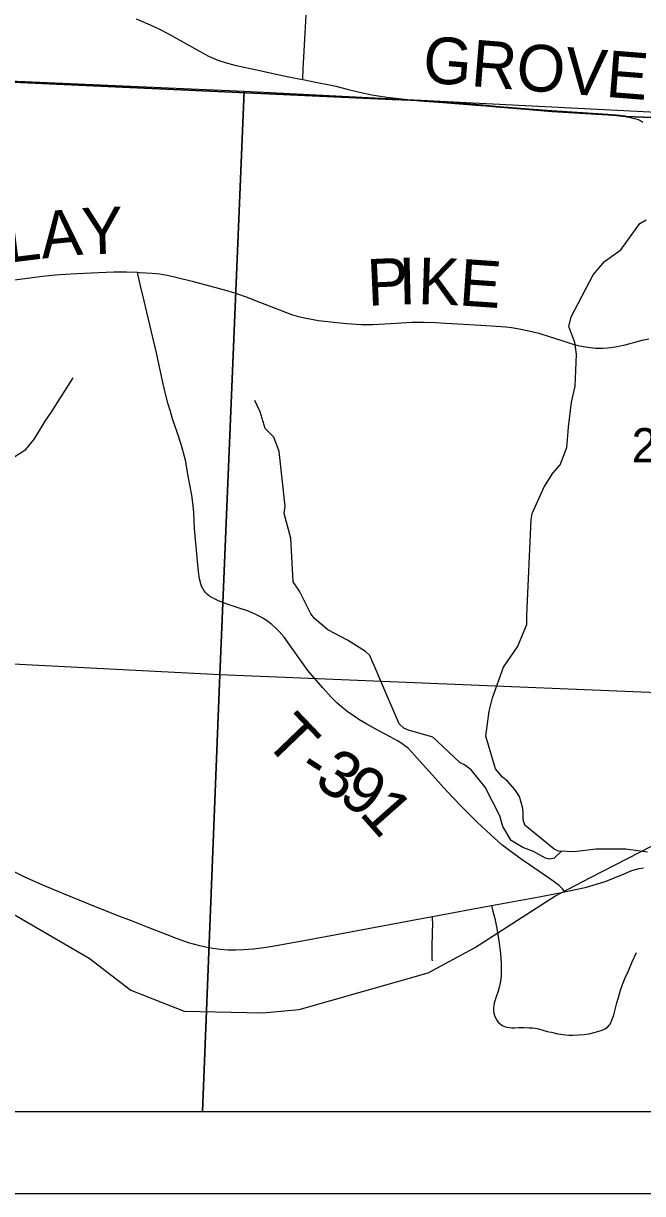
# Model space of a CAD drawing. Extents: x 0 to 34, y 0 to 22.
# Drawn here: x 3.463 to 4.217, y 14 to 15.425 of the extents above; entities that cross this region are included whole.
import ezdxf

# ---------------------------------------------------------------- set-up
doc = ezdxf.new("R2010")
doc.units = 0
for name, color, linetype in [('GM_X_County_Road', 7, 'Continuous'), ('GM_X_County_Road_Text', 7, 'Continuous'), ('GM_X_Minor_River', 7, 'Continuous'), ('GM_X_Rail_Line', 7, 'Continuous'), ('GM_X_Section', 7, 'Continuous'), ('GM_X_Section_Text', 7, 'Continuous'), ('GM_X_State_Route', 7, 'Continuous'), ('GM_X_Township_Road', 7, 'Continuous'), ('GM_X_Township_Road_Text', 7, 'Continuous'), ('GM_X_Unincorporated_Text', 7, 'Continuous'), ('SH_Data', 7, 'Continuous')]:
    doc.layers.add(name, color=color, linetype=linetype)

msp = doc.modelspace()

# ---------------------------------------------------------------- linework, layer by layer
at = {"layer": 'GM_X_County_Road'}
for points in [[(3.6001, 15.4304), (3.6172, 15.4233), (3.6284, 15.418), (3.6394, 15.4122), (3.6773, 15.391), (3.6882, 15.3851), (3.6938, 15.3825), (3.6995, 15.3802), (3.7083, 15.3774), (3.7203, 15.3743), (3.7506, 15.3676), (3.7779, 15.3617), (3.7961, 15.3578), (3.803, 15.3565)], [(3.803, 15.3565), (3.8205, 15.3532), (3.8334, 15.3506), (3.8434, 15.3484), (3.8571, 15.3451), (3.8719, 15.3411), (3.8871, 15.3381), (3.9054, 15.3351), (3.9236, 15.333), (3.9453, 15.3308), (3.9733, 15.3285), (4.0135, 15.3256), (4.0259, 15.3246), (4.0383, 15.3234), (4.0785, 15.3201), (4.1063, 15.3179), (4.1745, 15.3136), (4.1851, 15.3127), (4.1958, 15.3116), (4.1975, 15.3113), (4.2024, 15.3104), (4.2034, 15.3101)], [(4.2034, 15.3101), (4.2085, 15.3089), (4.2115, 15.3078), (4.2144, 15.3064), (4.2171, 15.3048)]]:
    msp.add_lwpolyline(points, dxfattribs=at)
at = {"layer": 'GM_X_Minor_River'}
for points in [[(4.2227, 14.4157), (4.1962, 14.4193), (4.1773, 14.4196), (4.1596, 14.4195), (4.1335, 14.4163), (4.1142, 14.417), (4.1092, 14.4192), (4.0735, 14.4486), (4.0712, 14.4555), (4.0712, 14.4638), (4.0708, 14.4691), (4.0669, 14.4835), (4.0612, 14.4922), (4.0521, 14.5024), (4.046, 14.507), (4.0376, 14.5172), (4.0257, 14.557), (4.0301, 14.5874), (4.0338, 14.6037), (4.0472, 14.641), (4.0645, 14.6658), (4.0757, 14.6928), (4.0756, 14.7038), (4.0811, 14.8208), (4.0822, 14.828), (4.0964, 14.86), (4.1073, 14.8771), (4.1163, 14.8874), (4.1245, 14.9087), (4.1259, 14.9281), (4.1263, 14.9334), (4.1303, 14.9638), (4.1347, 14.9832), (4.1364, 15.0223), (4.1341, 15.0364), (4.1268, 15.0561), (4.1298, 15.0675), (4.1564, 15.1189), (4.1703, 15.1349), (4.1902, 15.1494), (4.2132, 15.1815), (4.2211, 15.1857)], [(3.4433, 14.8917), (3.4656, 14.9063), (3.4765, 14.9193), (3.4892, 14.9406), (3.4964, 14.9513), (3.5234, 14.9932)], [(4.1181, 14.4168), (4.1089, 14.4086), (4.1036, 14.4074), (4.0983, 14.4085), (4.0839, 14.4164), (4.071, 14.4213), (4.0566, 14.4299), (4.0467, 14.447), (4.0428, 14.4599), (4.0249, 14.4951), (4.0078, 14.5159), (3.9998, 14.5223), (3.9945, 14.5245), (3.9667, 14.5509), (3.9614, 14.5559), (3.9315, 14.5644), (3.9258, 14.5667), (3.9205, 14.572), (3.8956, 14.6295), (3.8937, 14.6345), (3.8845, 14.6553), (3.8795, 14.6602), (3.8575, 14.6741), (3.8336, 14.6865), (3.8173, 14.7001), (3.8127, 14.7058), (3.799, 14.7334), (3.7913, 14.7448), (3.7884, 14.7983), (3.7803, 14.8283), (3.7814, 14.837), (3.7743, 14.9038), (3.7677, 14.9212), (3.7571, 14.9318), (3.7509, 14.9519), (3.7444, 14.9659)]]:
    msp.add_lwpolyline(points, dxfattribs=at)
at = {"layer": 'GM_X_Rail_Line'}
for points in [[(2.1, 18.4819), (2.1, 15.4153), (3.9123, 15.3323), (3.9451, 15.3313), (3.973, 15.329), (4.0133, 15.3262), (4.0257, 15.3251), (4.0381, 15.324), (4.0782, 15.3206), (4.1061, 15.3185), (4.1743, 15.3141), (4.1849, 15.3132), (4.1956, 15.3121), (4.1973, 15.3118), (5.1044, 15.2759), (5.2458, 15.271), (5.4522, 15.2638), (5.479, 15.731), (5.4821, 15.8189)], [(3.3777, 14.3824), (3.5429, 14.2865), (3.5938, 14.2475), (3.6586, 14.2221), (3.7541, 14.2201), (3.7984, 14.2243), (3.9556, 14.269), (4.0121, 14.2992), (4.11, 14.362), (4.1532, 14.3849), (4.2282, 14.4236)]]:
    msp.add_lwpolyline(points, dxfattribs=at)
msp.add_lwpolyline([(2.1, 15.4153), (2.1, 14.1), (6.4223, 14.1), (6.4607, 14.8895), (6.4764, 15.22), (6.2705, 15.2288), (5.4522, 15.2638), (5.2458, 15.271), (5.1044, 15.2759), (4.1973, 15.3118), (4.1956, 15.3121), (4.1849, 15.3132), (4.1743, 15.3141), (4.1061, 15.3185), (4.0782, 15.3206), (4.0381, 15.324), (4.0257, 15.3251), (4.0133, 15.3262), (3.973, 15.329), (3.9451, 15.3313), (3.9123, 15.3323)], close=True, dxfattribs=at)
at = {"layer": 'GM_X_Section'}
for points in [[(2.9571, 15.3766), (3.7314, 15.3424), (3.7021, 14.6318), (2.6704, 14.6848), (2.7035, 15.3864)], [(3.7314, 15.3424), (4.7434, 15.2908), (4.7084, 14.5904), (3.7021, 14.6318)]]:
    msp.add_lwpolyline(points, close=True, dxfattribs=at)
at = {"layer": 'GM_X_State_Route'}
for points in [[(3.3886, 14.423), (3.4633, 14.3863), (3.4862, 14.3758), (3.5103, 14.3657), (3.5392, 14.3542), (3.5766, 14.3391), (3.594, 14.3324), (3.6142, 14.3244), (3.6373, 14.3153), (3.6489, 14.3109), (3.6636, 14.3059), (3.6754, 14.3024), (3.6845, 14.3004), (3.6936, 14.2989), (3.7028, 14.2977), (3.7121, 14.297), (3.7213, 14.2968), (3.7306, 14.2971), (3.7429, 14.2981), (3.7583, 14.3001), (3.7705, 14.3021), (3.8132, 14.3098), (3.8437, 14.3154), (3.8892, 14.3239), (3.9411, 14.3336), (3.9611, 14.3374), (3.9655, 14.3382), (3.9868, 14.3422), (4.0082, 14.3462), (4.0327, 14.3507), (4.0906, 14.3613), (4.1219, 14.3676)], [(4.1219, 14.3676), (4.1235, 14.3679), (4.1484, 14.373), (4.1607, 14.3766), (4.1723, 14.3806), (4.1944, 14.3895), (4.2038, 14.3933), (4.2127, 14.3957), (4.2179, 14.3968)]]:
    msp.add_lwpolyline(points, dxfattribs=at)
at = {"layer": 'GM_X_Township_Road'}
for points in [[(3.803, 15.3565), (3.8035, 15.3698), (3.8054, 15.406), (3.8066, 15.4278), (3.8076, 15.4435), (3.8084, 15.4595), (3.8095, 15.4744), (3.8096, 15.4773), (3.8092, 15.4803), (3.8084, 15.4831), (3.8074, 15.486), (3.8063, 15.4886), (3.8052, 15.4913), (3.8042, 15.4942), (3.8031, 15.4971), (3.8018, 15.4999)], [(3.1754, 15.0509), (3.1797, 15.0533), (3.1907, 15.059), (3.1993, 15.0629), (3.2081, 15.0662), (3.2171, 15.0689), (3.2352, 15.0733), (3.2566, 15.0776), (3.3002, 15.0864), (3.3873, 15.103), (3.403, 15.1051), (3.4306, 15.1094), (3.4552, 15.113), (3.486, 15.1172), (3.5015, 15.1188), (3.5201, 15.1201), (3.5543, 15.1218), (3.5729, 15.1225), (3.5885, 15.1224), (3.6017, 15.1219)], [(4.1219, 14.3676), (4.119, 14.3709), (4.1167, 14.3735), (4.115, 14.3751), (4.1061, 14.3815), (4.0904, 14.3925), (4.0701, 14.4064), (4.055, 14.4172), (4.0453, 14.4248), (4.0315, 14.4371), (4.0158, 14.4519), (3.9954, 14.472), (3.9787, 14.4898), (3.939, 14.5338), (3.9316, 14.5419), (3.9285, 14.5444), (3.9262, 14.5462), (3.9237, 14.5481), (3.9183, 14.5515), (3.9094, 14.5564), (3.9026, 14.5598), (3.8918, 14.5657), (3.881, 14.5716), (3.8712, 14.5775), (3.8669, 14.5805), (3.8588, 14.5859), (3.8506, 14.5922), (3.8445, 14.5977), (3.8376, 14.6046), (3.8275, 14.6159), (3.8093, 14.6371), (3.8, 14.6495), (3.7893, 14.6648), (3.7802, 14.6774), (3.7743, 14.6845), (3.7699, 14.6889), (3.7653, 14.693), (3.7603, 14.6968), (3.7552, 14.7002), (3.7498, 14.7033), (3.7443, 14.706), (3.7356, 14.7095), (3.7268, 14.7125), (3.7121, 14.7175), (3.7005, 14.722), (3.6948, 14.7246), (3.6921, 14.726), (3.6895, 14.7277), (3.687, 14.7296), (3.6848, 14.7317), (3.6828, 14.7341), (3.6811, 14.7367), (3.6797, 14.7395), (3.6787, 14.7424), (3.6773, 14.7485), (3.676, 14.7577), (3.6749, 14.7701), (3.6713, 14.8101), (3.6704, 14.8288), (3.6695, 14.838), (3.6678, 14.8503), (3.664, 14.8717), (3.6601, 14.8931), (3.6579, 14.9022), (3.6552, 14.9111), (3.6504, 14.9259), (3.6445, 14.9435), (3.6417, 14.9523), (3.6392, 14.9613), (3.6353, 14.9755), (3.6326, 14.9875), (3.6247, 15.0239), (3.6183, 15.0511), (3.6099, 15.0873), (3.6055, 15.1054), (3.6034, 15.1145), (3.6017, 15.1219)], [(3.6017, 15.1219), (3.604, 15.1218), (3.6195, 15.121), (3.6242, 15.1205), (3.6288, 15.12), (3.6329, 15.1193), (3.6381, 15.1184), (3.6502, 15.1157), (3.6684, 15.1111), (3.7104, 15.0999), (3.7223, 15.0962), (3.7341, 15.0921), (3.7515, 15.0853), (3.7745, 15.076), (3.7891, 15.0706), (3.7979, 15.0679), (3.8069, 15.0659), (3.8222, 15.0634), (3.8406, 15.061), (3.856, 15.0594), (3.8745, 15.0583), (3.8881, 15.0582), (3.9099, 15.0596), (3.9356, 15.0611), (3.9509, 15.0613), (3.9644, 15.0606), (3.9771, 15.0599), (3.9918, 15.0591), (4.0196, 15.0574), (4.0385, 15.0564), (4.0502, 15.0554), (4.0571, 15.0546), (4.0643, 15.0535), (4.0784, 15.0505), (4.0905, 15.0476), (4.103, 15.0437), (4.1173, 15.0394), (4.1292, 15.0353), (4.1377, 15.0329), (4.1445, 15.0314), (4.1501, 15.0306), (4.1593, 15.0297), (4.1684, 15.0295), (4.1745, 15.0299), (4.1836, 15.0311), (4.1956, 15.0336), (4.2162, 15.0392), (4.2242, 15.0409)], [(4.0327, 14.3507), (4.0344, 14.344), (4.0367, 14.335), (4.0392, 14.3229), (4.0417, 14.3076), (4.0435, 14.2923), (4.0444, 14.2801), (4.0446, 14.2708), (4.0444, 14.2647), (4.0436, 14.2586), (4.0424, 14.2525), (4.0409, 14.2466), (4.0389, 14.2407), (4.0369, 14.2349), (4.0361, 14.2319), (4.0354, 14.2289), (4.0351, 14.2258), (4.0352, 14.2228), (4.0356, 14.2197), (4.0364, 14.2167), (4.0375, 14.2139), (4.0391, 14.2112), (4.0409, 14.2087), (4.0432, 14.2066), (4.0457, 14.2048), (4.0484, 14.2035), (4.0514, 14.2026), (4.0544, 14.2021), (4.0575, 14.202), (4.0607, 14.202), (4.0662, 14.2023), (4.0724, 14.2023), (4.0786, 14.202), (4.0825, 14.2017), (4.086, 14.2013), (4.09, 14.2004), (4.0953, 14.1991), (4.0992, 14.1979), (4.1025, 14.1971), (4.1059, 14.1964), (4.1089, 14.1956), (4.1133, 14.1947), (4.1171, 14.194), (4.1201, 14.1935), (4.1234, 14.1931), (4.127, 14.193), (4.1318, 14.1928), (4.1384, 14.1931), (4.1457, 14.1938), (4.1518, 14.1947), (4.1578, 14.1961), (4.1635, 14.1978), (4.1662, 14.1987), (4.169, 14.1998), (4.1708, 14.2006), (4.1727, 14.2018), (4.1743, 14.203), (4.1761, 14.205), (4.1772, 14.2064), (4.1789, 14.2098), (4.1815, 14.2175), (4.1842, 14.2272), (4.1855, 14.2323), (4.1872, 14.2387), (4.1898, 14.2475), (4.1923, 14.2544), (4.1955, 14.2627), (4.1995, 14.2712), (4.2042, 14.282), (4.2094, 14.2937)], [(3.9609, 14.2833), (3.9607, 14.2864), (3.9605, 14.2927), (3.9606, 14.3), (3.961, 14.3175), (3.9612, 14.3291), (3.9611, 14.3341), (3.9611, 14.3374)]]:
    msp.add_lwpolyline(points, dxfattribs=at)
at = {"layer": 'GM_X_Unincorporated_Text'}
for points in [[(2.641, 14.1), (3.681, 14.1), (3.7021, 14.6318), (2.6704, 14.6848)], [(3.681, 14.1), (4.6857, 14.1), (4.7084, 14.5904), (3.7021, 14.6318)]]:
    msp.add_lwpolyline(points, close=True, dxfattribs=at)
at = {"layer": 'SH_Data'}
for p, q in [((2.1, 14.1), (8.9, 14.1)), ((2, 14), (9, 14))]:
    msp.add_line(p, q, dxfattribs=at)

# ---------------------------------------------------------------- texts
at = {"layer": 'GM_X_County_Road_Text'}
msp.add_text('GROVE', height=0.05682, rotation=355.4646, dxfattribs=at).set_placement((3.9478, 15.3534))
at = {"layer": 'GM_X_Section_Text'}
msp.add_text('2', height=0.0419, rotation=0, dxfattribs=at).set_placement((4.2034, 14.8903))
at = {"layer": 'GM_X_Township_Road_Text'}
for s, rotation, p in [('L', 7.0894, (3.4439, 15.1333)), ('A', 5.7102, (3.4857, 15.1385)), ('Y', 2.0805, (3.5345, 15.1434)), ('P', 2.5905, (3.8823, 15.081)), ('I', 1.3505, (3.9202, 15.0827)), ('K', 358.1674, (3.9427, 15.0833)), ('E', 356.1013, (3.9922, 15.0817)), ('T', 313.8545, (3.7541, 14.5506)), ('3', 328.1279, (3.8151, 14.4975)), ('-', 326.7602, (3.7943, 14.5111)), ('9', 326.4124, (3.8444, 14.4792)), ('1', 311.5056, (3.8706, 14.4624))]:
    msp.add_text(s, height=0.0568, rotation=rotation, dxfattribs=at).set_placement(p)

doc.saveas('drawing.dxf')
